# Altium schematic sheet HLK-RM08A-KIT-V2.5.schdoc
size A3
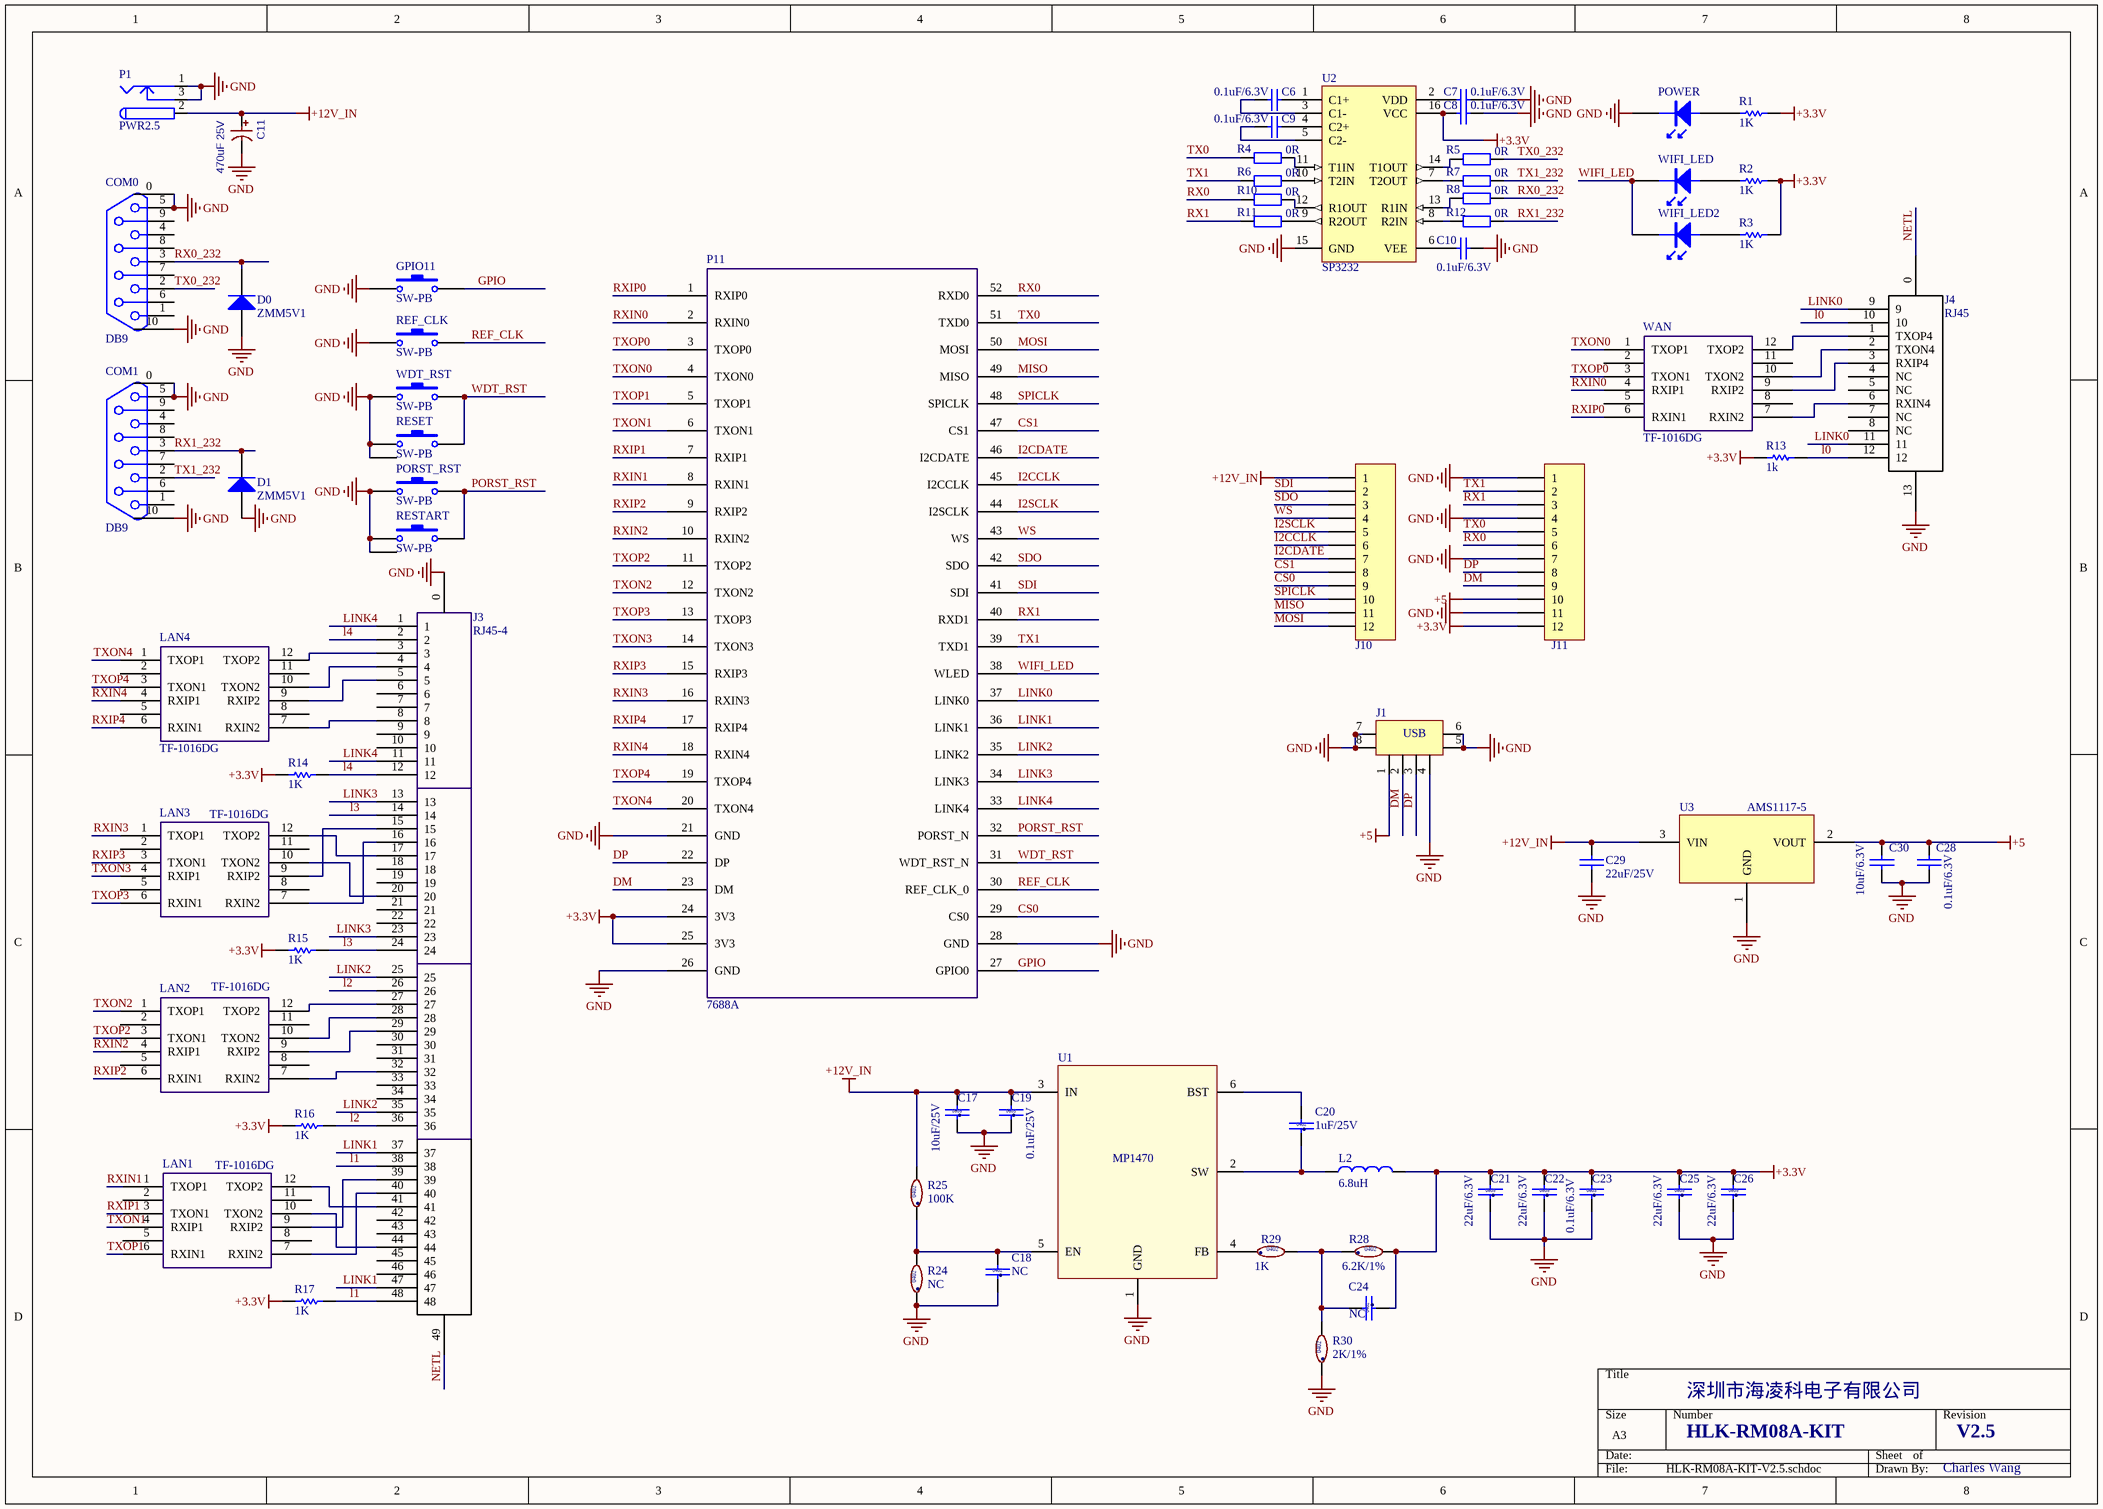
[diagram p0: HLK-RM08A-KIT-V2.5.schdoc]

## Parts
C6  0.1uF/6.3V  [0603]
C7  0.1uF/6.3V  [0603]
C8  0.1uF/6.3V  [0603]
C9  0.1uF/6.3V  [0603]
C10  0.1uF/6.3V  [0603]
C11  470uF 25V  [1000uF 8*12 电解电容]
C17  10uF/25V  [0805]
C18  NC  [0402]
C19  0.1uF/25V  [0603]
C20  1uF/25V  [0402]
C21  22uF/6.3V  [0805]
C22  22uF/6.3V  [0805]
C23  0.1uF/6.3V  [0603]
C24  NC  [0402]
C25  22uF/6.3V  [0805]
C26  22uF/6.3V  [0805]
C28  0.1uF/6.3V  [0603]
C29  22uF/25V  [0603]
C30  10uF/6.3V  [0603]
COM0  DB9  [DB9s]
COM1  DB9  [DB9s]
D0  ZMM5V1  [1005D]
D1  ZMM5V1  [1005D]
GPIO11  SW-PB  [SWITCH]
J1  USB  [USB/4P/P2.0/DIP/R/F/SUA-110VB-B2N]
J3  RJ45-4  [RJ45-4-LED]
J4  RJ45
J10  2.54*16  [HDR1X12]  (value not drawn)
J11  2.54*16  [HDR1X12]  (value not drawn)
L2  6.8uH  [4.7uH SMD,5.8x5.2x4.5mm]
LAN1  TF-1016DG  [tf-1016dg]
LAN2  TF-1016DG  [tf-1016dg]
LAN3  TF-1016DG  [tf-1016dg]
LAN4  TF-1016DG  [tf-1016dg]
P1  PWR2.5  [POWER_STK1]
P11  7688A  [RM08K_52pin]
PORST_RST  SW-PB  [SWITCH]
POWER  (no value)  [0603LED]
R1  1K  [0603]
R2  1K  [0603]
R3  1K  [0603]
R4  0R  [0603]
R5  0R  [0603]
R6  0R  [0603]
R7  0R  [0603]
R8  0R  [0603]
R10  0R  [0603]
R11  0R  [0603]
R12  0R  [0603]
R13  1K  [0603]
R14  1K  [0603]
R15  1K  [0603]
R16  1K  [0603]
R17  1K  [0603]
R24  NC  [0402]
R25  100K  [0402]
R28  6.2K/1%  [0402]
R29  1K  [0402]
R30  2K/1%  [0402]
REF_CLK  SW-PB  [SWITCH]
RESET  SW-PB  [K5]
RESTART  SW-PB  [K5]
U1  MP1470  [MP1470]
U2  SP3232  [MAX3232]
U3  AMS1117-5  [AMS1117]
WAN  TF-1016DG  [tf-1016dg]
WDT_RST  SW-PB  [SWITCH]
WIFI_LED  (no value)  [0603LED]
WIFI_LED2  (no value)  [LED0.2]

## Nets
+3.3V: C8.1 C21.2 C22.2 C23.2 C24.1 C25.2 C26.2 J11.12 L2.2 P11.24(3V3) P11.25(3V3) R1.2 R2.2 R3.2 R13.2 R14.2 R15.2 R16.2 R17.2 R28.2 U2.16(VCC)
+5: C28.1 C30.1 J1.1 J11.10 U3.2(VOUT)
+12V_IN: C11.1 C17.2 C19.2 C29.1 J10.1 P1.2 R25.2 U1.3(IN) U3.3(VIN)
GND: C7.2 C8.2 C10.1 C11.2 C17.1 C18.1 C19.1 C21.1 C22.1 C23.1 C25.1 C26.1 C28.2 C29.2 C30.2 COM0.0 COM0.5 COM0.10 COM1.0 COM1.5 COM1.10 D0.1(A) D1.1(A) GPIO11.1 J1.4 J1.5 J1.6 J1.7 J1.8 J3.0 J4.13 J11.1 J11.4 J11.7 J11.11 P1.1 P1.3 P11.21(GND) P11.26(GND) P11.28(GND) PORST_RST.1 POWER.2 R24.1 R30.1 REF_CLK.1 RESET.1 RESET.3 RESTART.1 RESTART.3 U1.1(GND) U2.15(GND) U3.1(GND) WDT_RST.1
CS0: J10.9 P11.29(CS0)
CS1: J10.8 P11.47(CS1)
DM: J1.2 J11.9 P11.23(DM)
DP: J1.3 J11.8 P11.22(DP)
GPIO: GPIO11.2 P11.27(GPIO0)
I2CCLK: J10.6 P11.45(I2CCLK)
I2CDATE: J10.7 P11.46(I2CDATE)
I2SCLK: J10.5 P11.44(I2SCLK)
l0: J4.10 J4.12 R13.1
l1: J3.38 J3.48 R17.1
l2: J3.26 J3.36 R16.1
l3: J3.14 J3.24 R15.1
l4: J3.2 J3.12 R14.1
LINK0: J4.9 J4.11 P11.37(LINK0)
LINK1: J3.37 J3.47 P11.36(LINK1)
LINK2: J3.25 J3.35 P11.35(LINK2)
LINK3: J3.13 J3.23 P11.34(LINK3)
LINK4: J3.1 J3.11 P11.33(LINK4)
MISO: J10.11 P11.49(MISO)
MOSI: J10.12 P11.50(MOSI)
NETL: J3.49 J4.0
PORST_RST: P11.32(PORST_N) PORST_RST.2 RESTART.2
REF_CLK: P11.30(REF_CLK_0) REF_CLK.2
RX0: J11.6 P11.52(RXD0) R10.1
RX0_232: COM0.3 D0.2(K) R8.2
RX1: J11.3 P11.40(RXD1) R11.1
RX1_232: COM1.3 D1.2(K) R12.2
RXIN0: P11.2(RXIN0) WAN.4(RXIP1)
RXIN1: LAN1.1(TXOP1) P11.8(RXIN1)
RXIN2: LAN2.4(RXIP1) P11.10(RXIN2)
RXIN3: LAN3.1(TXOP1) P11.16(RXIN3)
RXIN4: LAN4.4(RXIP1) P11.18(RXIN4)
RXIP0: P11.1(RXIP0) WAN.6(RXIN1)
RXIP1: LAN1.3(TXON1) P11.7(RXIP1)
RXIP2: LAN2.6(RXIN1) P11.9(RXIP2)
RXIP3: LAN3.3(TXON1) P11.15(RXIP3)
RXIP4: LAN4.6(RXIN1) P11.17(RXIP4)
SDI: J10.2 P11.41(SDI)
SDO: J10.3 P11.42(SDO)
SPICLK: J10.10 P11.48(SPICLK)
TX0: J11.5 P11.51(TXD0) R4.1
TX0_232: COM0.2 R5.2
TX1: J11.2 P11.39(TXD1) R6.1
TX1_232: COM1.2 R7.2
TXON0: P11.4(TXON0) WAN.1(TXOP1)
TXON1: LAN1.4(RXIP1) P11.6(TXON1)
TXON2: LAN2.1(TXOP1) P11.12(TXON2)
TXON3: LAN3.4(RXIP1) P11.14(TXON3)
TXON4: LAN4.1(TXOP1) P11.20(TXON4)
TXOP0: P11.3(TXOP0) WAN.3(TXON1)
TXOP1: LAN1.6(RXIN1) P11.5(TXOP1)
TXOP2: LAN2.3(TXON1) P11.11(TXOP2)
TXOP3: LAN3.6(RXIN1) P11.13(TXOP3)
TXOP4: LAN4.3(TXON1) P11.19(TXOP4)
WDT_RST: P11.31(WDT_RST_N) RESET.2 WDT_RST.2
WIFI_LED: P11.38(WLED) WIFI_LED.2 WIFI_LED2.2
WS: J10.4 P11.43(WS)
NetC6_1: C6.1 U2.3(C1-)
NetC6_2: C6.2 U2.1(C1+)
NetC7_1: C7.1 U2.2(VDD)
NetC9_1: C9.1 U2.5(C2-)
NetC9_2: C9.2 U2.4(C2+)
NetC10_2: C10.2 U2.6(VEE)
NetC18_2: C18.2 R24.2 R25.1 U1.5(EN)
NetC20_1: C20.1 L2.1 U1.2(SW)
NetC20_2: C20.2 U1.6(BST)
NetC24_2: C24.2 R28.1 R29.2 R30.2
NetJ3_3: J3.3 LAN4.12(TXOP2)
NetJ3_4: J3.4 LAN4.10(TXON2)
NetJ3_5: J3.5 LAN4.9(RXIP2)
NetJ3_8: J3.8 LAN4.7(RXIN2)
NetJ3_15: J3.15 LAN3.9(RXIP2)
NetJ3_16: J3.16 LAN3.7(RXIN2)
NetJ3_17: J3.17 LAN3.12(TXOP2)
NetJ3_20: J3.20 LAN3.10(TXON2)
NetJ3_27: J3.27 LAN2.12(TXOP2)
NetJ3_28: J3.28 LAN2.10(TXON2)
NetJ3_29: J3.29 LAN2.9(RXIP2)
NetJ3_32: J3.32 LAN2.7(RXIN2)
NetJ3_39: J3.39 LAN1.9(RXIP2)
NetJ3_40: J3.40 LAN1.7(RXIN2)
NetJ3_41: J3.41 LAN1.12(TXOP2)
NetJ3_44: J3.44 LAN1.10(TXON2)
NetJ4_1: J4.1(TXOP4) WAN.12(TXOP2)
NetJ4_2: J4.2(TXON4) WAN.10(TXON2)
NetJ4_3: J4.3(RXIP4) WAN.9(RXIP2)
NetJ4_6: J4.6(RXIN4) WAN.7(RXIN2)
NetPOWER_1: POWER.1 R1.1
NetR2_1: R2.1 WIFI_LED.1
NetR3_1: R3.1 WIFI_LED2.1
NetR4_2: R4.2 U2.11(T1IN)
NetR5_1: R5.1 U2.14(T1OUT)
NetR6_2: R6.2 U2.10(T2IN)
NetR7_1: R7.1 U2.7(T2OUT)
NetR8_1: R8.1 U2.13(R1IN)
NetR10_2: R10.2 U2.12(R1OUT)
NetR11_2: R11.2 U2.9(R2OUT)
NetR12_1: R12.1 U2.8(R2IN)
NetR29_1: R29.1 U1.4(FB)

Not connected (* = marked no-connect by the designer): COM0 1 4 6 7 8 9; COM1 1 4 6 7 8 9; J3 6 7 9 10 18 19 21 22 30 31 33 34 42 43 45 46; J4 4(NC) 5(NC) 7(NC) 8(NC); LAN1 2 5 8 11; LAN2 2 5 8 11; LAN3 2 5 8 11; LAN4 2 5 8 11; WAN 2 5 8 11

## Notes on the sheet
- 深圳市海凌科电子有限公司
- HLK-RM08A-KIT
- V2.5
- Charles Wang

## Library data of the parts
C6-C10 = Cap: Capacitor; Value: 100pF
C11 = 1000uF 8*12 电解电容: BOM_Manufacturer: ValuePro; BOM_Manufacturer Part: 1000uF 10V 8*12; nameAlias: Capacitance
C17 C21 C22 C25 C26 = C0805
C18 C20 C24 = C0402
C19 C23 = C0603
C28-C30 = CAP: Capacitor
D0 D1 = Diode: Default Diode
GPIO11 PORST_RST REF_CLK RESET RESTART WDT_RST = SW-PB: Switch
J1 = 2
J4 = RJ45_1
J10 J11 = CON16: Connector
L2 = INDUCTOR1
LAN1-LAN4 P11 WAN = Component_1
P1 = PWR2.5: Low Voltage Power Supply Connector
POWER WIFI_LED WIFI_LED2 = LED
R1-R3 R13-R17 = Res1: Resistor
R4-R8 R10-R12 = Res2: Resistor
R24 R25 R28-R30 = R0402
U2 = MAX232ACPE: +5V Powered, Multi-Channel RS-232 Driver/Receiver; PackageDocument: 1997
U3 = AMS1117-3.3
